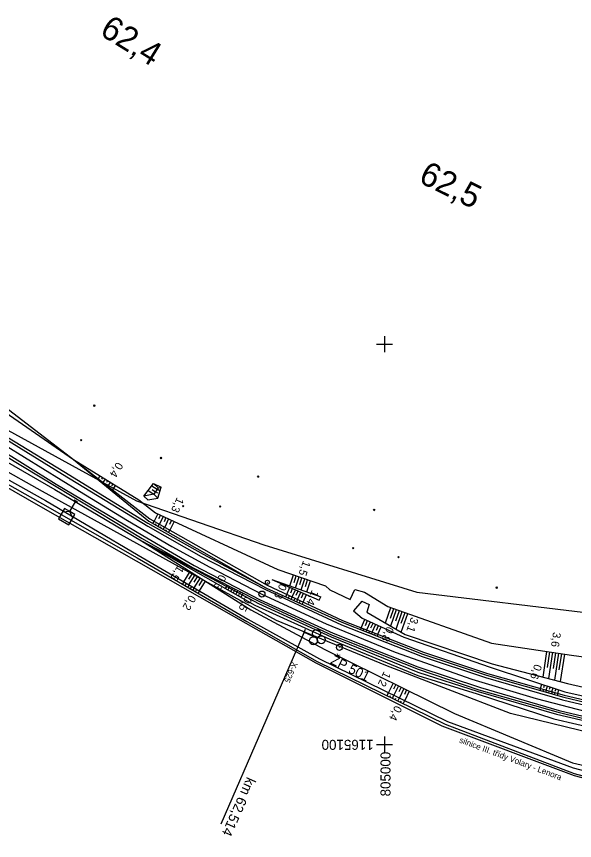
# Model space of a CAD drawing. Extents: x -805636 to -804553, y -1165340 to -1164656.
# Drawn here: x -805092 to -804952.6, y -1165124 to -1164918.2 of the extents above; entities that cross this region are included whole.
import ezdxf

# ---------------------------------------------------------------- set-up
doc = ezdxf.new("R2010")
doc.units = 0
for name, color, linetype in [('0381KM061-064P - Vrstva 1', 7, 'Continuous'), ('0381KM061-064P - Vrstva 4', 7, 'Continuous'), ('0381KM061-064P - Vrstva 48', 7, 'Continuous'), ('0381KM061-064P - Vrstva 49', 7, 'Continuous'), ('0381KM061-064P - Vrstva 51', 7, 'Continuous'), ('0381KM061-064P - Vrstva 7', 7, 'Continuous'), ('0381KM061-064P - Vrstva 8', 7, 'Continuous'), ('hran DP - hran DP', 7, 'Continuous'), ('krizky_1000 - souradnice', 7, 'Continuous'), ('krizky_1000 - Vrstva 1', 7, 'Continuous'), ('vyt_sit - stávající', 7, 'Continuous')]:
    doc.layers.add(name, color=color, linetype=linetype)

msp = doc.modelspace()

# ---------------------------------------------------------------- linework, layer by layer
at = {"layer": '0381KM061-064P - Vrstva 1'}
for points in [[(-805131.47, -1165002.7), (-805117.01, -1165011.6), (-805094.55, -1165025.46), (-805076.19, -1165036.77)], [(-805076.19, -1165036.77), (-805064.24, -1165044.04), (-805053.13, -1165050.53)], [(-805053.13, -1165050.53), (-805043.64, -1165055.76), (-805030.64, -1165062.45), (-805014.61, -1165069.88), (-804997.39, -1165076.92), (-804978.26, -1165083.66), (-804962.13, -1165088.54), (-804947.73, -1165092.28), (-804936.17, -1165094.91), (-804922.95, -1165097.46), (-804911.85, -1165099.22)]]:
    msp.add_lwpolyline(points, dxfattribs=at)
at = {"layer": '0381KM061-064P - Vrstva 4'}
for points in [[(-805257.4, -1164945.18), (-805227.5, -1164957.9), (-805205.55, -1164967.2), (-805161.7, -1164987.26), (-805121.4, -1165011.84), (-805082.08, -1165035.58)], [(-805257.21, -1164944.39), (-805227.21, -1164957.06), (-805205.17, -1164966.48), (-805161.59, -1164986.72), (-805120.84, -1165010.88), (-805082.03, -1165034.98)], [(-805187.57, -1164970.92), (-805160.12, -1164984.24), (-805119.58, -1165008.37), (-805080.47, -1165032.5)], [(-805187.4, -1164970.45), (-805159.98, -1164983.82), (-805119.44, -1165007.96), (-805080.11, -1165031.8)], [(-805080.11, -1165031.8), (-805059.18, -1165044.72), (-805045.31, -1165052.51), (-805029.54, -1165060.96), (-805010.72, -1165069.47), (-804990.45, -1165077.48), (-804974.57, -1165082.73), (-804955.28, -1165088.2), (-804932.96, -1165093.51), (-804912.39, -1165097.1), (-804892.28, -1165099.85)], [(-805080.47, -1165032.5), (-805059.19, -1165045.48), (-805045.86, -1165053.03), (-805029.76, -1165061.31), (-805010.76, -1165070.1), (-804990.66, -1165078.03), (-804974.85, -1165083.28), (-804955.57, -1165088.82), (-804933.31, -1165094.09), (-804912.36, -1165097.73), (-804892.37, -1165100.24)], [(-805082.08, -1165035.58), (-805060.58, -1165048.58), (-805047.98, -1165055.77), (-805031.23, -1165064.28), (-805013.07, -1165072.73), (-804991.62, -1165081.24), (-804976.47, -1165086.37), (-804956.64, -1165091.96), (-804934.05, -1165097.54), (-804913.13, -1165101.06), (-804892.22, -1165103.81)], [(-805082.03, -1165034.98), (-805060.37, -1165047.85), (-805047.54, -1165055.28), (-805031.06, -1165063.92), (-805012.89, -1165072.24), (-804991.69, -1165080.62), (-804976.05, -1165085.82), (-804956.42, -1165091.49), (-804933.87, -1165096.82), (-804912.82, -1165100.43), (-804892.24, -1165103.28)]]:
    msp.add_lwpolyline(points, dxfattribs=at)
at = {"layer": '0381KM061-064P - Vrstva 48'}
for p, q in [((-805071.7, -1165033.78), (-805071.58, -1165033.63)), ((-805071.12, -1165032.94), (-805071.56, -1165033.64)), ((-805070.48, -1165033.33), (-805070.72, -1165033.72)), ((-805069.84, -1165033.72), (-805070.36, -1165034.57)), ((-805071.12, -1165034.26), (-805071.05, -1165034.17)), ((-805070.54, -1165034.73), (-805070.39, -1165034.55)), ((-805069.96, -1165035.21), (-805069.88, -1165035.11)), ((-805069.21, -1165034.12), (-805069.49, -1165034.57)), ((-805069.38, -1165035.68), (-805069.2, -1165035.47)), ((-805068.57, -1165034.51), (-805069.17, -1165035.49)), ((-805067.93, -1165034.91), (-805068.25, -1165035.43)), ((-805067.29, -1165035.3), (-805067.98, -1165036.41)), ((-805058.16, -1165035.39), (-805056.82, -1165036.27)), ((-805068.8, -1165036.16), (-805068.71, -1165036.04)), ((-805068.22, -1165036.63), (-805068.02, -1165036.38)), ((-805059.08, -1165036.56), (-805057.62, -1165037.51)), ((-805058.06, -1165036.34), (-805057.22, -1165036.89)), ((-805056.69, -1165037.24), (-805057.22, -1165036.89)), ((-805056.11, -1165036.74), (-805056.82, -1165036.27)), ((-805056.69, -1165042.41), (-805057.55, -1165044.27)), ((-805056.01, -1165042.72), (-805056.45, -1165043.68)), ((-805055.32, -1165043.04), (-805056.24, -1165045.01)), ((-805054.64, -1165043.35), (-805055.11, -1165044.37)), ((-805053.96, -1165043.67), (-805054.93, -1165045.76)), ((-805053.28, -1165043.99), (-805053.78, -1165045.05)), ((-805057.91, -1165044.8), (-805057.59, -1165044.25)), ((-805057.26, -1165045.18), (-805057.1, -1165044.9)), ((-805056.61, -1165045.55), (-805056.29, -1165044.99)), ((-805055.96, -1165045.92), (-805055.8, -1165045.64)), ((-805055.31, -1165046.29), (-805054.98, -1165045.72)), ((-805052.6, -1165044.3), (-805053.62, -1165046.5)), ((-805054.65, -1165046.66), (-805054.49, -1165046.38)), ((-805054, -1165047.03), (-805053.68, -1165046.46)), ((-805050.18, -1165059.36), (-805048.58, -1165056.81)), ((-805048.9, -1165058.73), (-805047.94, -1165057.21)), ((-805048.89, -1165060.12), (-805047.31, -1165057.61)), ((-805047.61, -1165059.5), (-805046.68, -1165058.01)), ((-805047.59, -1165060.88), (-805046.04, -1165058.41)), ((-805023.71, -1165060.37), (-805022.78, -1165057.65)), ((-805022.63, -1165059.53), (-805022.07, -1165057.89)), ((-805022.3, -1165060.87), (-805021.36, -1165058.14)), ((-805021.22, -1165060.02), (-805020.66, -1165058.38)), ((-805020.89, -1165061.37), (-805019.95, -1165058.62)), ((-805050.16, -1165059.38), (-805050.49, -1165059.95)), ((-805049.64, -1165059.98), (-805049.84, -1165060.32)), ((-805048.86, -1165060.13), (-805049.19, -1165060.7)), ((-805046.33, -1165060.28), (-805045.41, -1165058.81)), ((-805046.29, -1165061.63), (-805044.77, -1165059.21)), ((-805039.53, -1165060.53), (-805039.82, -1165061.03)), ((-805039.51, -1165060.54), (-805039.32, -1165060.17)), ((-805038.77, -1165060.74), (-805038.65, -1165060.51)), ((-805019.81, -1165060.52), (-805019.24, -1165058.87)), ((-805019.48, -1165061.86), (-805018.53, -1165059.11)), ((-805048.35, -1165060.74), (-805048.55, -1165061.08)), ((-805047.57, -1165060.89), (-805047.9, -1165061.46)), ((-805047.05, -1165061.49), (-805047.25, -1165061.83)), ((-805046.27, -1165061.65), (-805046.6, -1165062.21)), ((-805038.99, -1165061.09), (-805039.17, -1165061.4)), ((-805038.21, -1165061.24), (-805038.52, -1165061.77)), ((-805038.18, -1165061.25), (-805037.98, -1165060.85)), ((-805037.68, -1165061.81), (-805037.86, -1165062.14)), ((-805037.44, -1165061.44), (-805037.31, -1165061.19)), ((-805036.89, -1165061.95), (-805037.21, -1165062.51)), ((-805036.86, -1165061.96), (-805036.64, -1165061.53)), ((-805036.36, -1165062.53), (-805036.56, -1165062.88)), ((-805036.11, -1165062.14), (-805035.97, -1165061.87)), ((-805035.57, -1165062.66), (-805035.91, -1165063.25)), ((-805035.54, -1165062.67), (-805035.3, -1165062.21)), ((-805024.47, -1165062.52), (-805024.74, -1165063.13)), ((-805024.46, -1165062.53), (-805023.69, -1165060.75)), ((-805023.47, -1165062.13), (-805023, -1165061.05)), ((-805023.1, -1165063.16), (-805022.31, -1165061.35)), ((-805022.1, -1165062.75), (-805021.62, -1165061.65)), ((-805021.74, -1165063.8), (-805020.94, -1165061.95)), ((-805020.74, -1165063.37), (-805020.25, -1165062.25)), ((-805020.39, -1165064.44), (-805019.56, -1165062.55)), ((-805023.9, -1165063.08), (-805024.06, -1165063.44)), ((-805023.11, -1165063.16), (-805023.37, -1165063.75)), ((-805022.53, -1165063.71), (-805022.69, -1165064.05)), ((-805021.75, -1165063.79), (-805022.01, -1165064.36)), ((-805021.17, -1165064.34), (-805021.32, -1165064.67)), ((-805020.39, -1165064.43), (-805020.64, -1165064.98)), ((-804999.81, -1165069.65), (-804998.44, -1165065.79)), ((-804998.58, -1165068.43), (-804997.73, -1165066.04)), ((-804998.48, -1165070.41), (-804997.03, -1165066.29)), ((-804997.22, -1165069.09), (-804996.32, -1165066.54)), ((-804997.16, -1165071.17), (-804995.61, -1165066.79)), ((-805005.89, -1165070.86), (-805004.93, -1165068.76)), ((-804995.86, -1165069.75), (-804994.91, -1165067.04)), ((-804995.84, -1165071.94), (-804994.2, -1165067.29)), ((-805005.88, -1165070.86), (-805006.06, -1165071.31)), ((-805004.81, -1165070.31), (-805004.25, -1165069.07)), ((-805004.49, -1165071.4), (-805003.57, -1165069.38)), ((-805003.43, -1165070.88), (-805002.89, -1165069.69)), ((-805003.1, -1165071.95), (-805002.21, -1165070)), ((-805002.05, -1165071.46), (-805001.53, -1165070.31)), ((-805001.7, -1165072.49), (-805000.85, -1165070.62)), ((-805005.26, -1165071.31), (-805005.36, -1165071.58)), ((-805004.49, -1165071.41), (-805004.67, -1165071.86)), ((-805003.86, -1165071.86), (-805003.97, -1165072.13)), ((-805003.09, -1165071.95), (-805003.27, -1165072.41)), ((-805002.46, -1165072.41), (-805002.57, -1165072.68)), ((-805001.69, -1165072.5), (-805001.88, -1165072.96)), ((-804960.43, -1165083.16), (-804959.47, -1165076.75)), ((-804959.31, -1165080.75), (-804958.72, -1165076.86)), ((-804958.97, -1165083.54), (-804957.98, -1165076.97)), ((-804957.84, -1165081.07), (-804957.24, -1165077.09)), ((-804957.51, -1165083.92), (-804956.5, -1165077.2)), ((-804956.37, -1165081.39), (-804955.76, -1165077.31)), ((-804956.05, -1165084.29), (-804955.02, -1165077.42)), ((-804997.87, -1165084.72), (-804999.02, -1165087.05)), ((-804997.2, -1165085.05), (-804997.77, -1165086.21)), ((-804996.53, -1165085.38), (-804997.68, -1165087.71)), ((-804961.1, -1165086), (-804960.76, -1165084.96)), ((-804960.24, -1165085.8), (-804960.04, -1165085.2)), ((-804999.41, -1165087.84), (-804999.02, -1165087.05)), ((-804995.85, -1165085.71), (-804996.43, -1165086.88)), ((-804995.18, -1165086.05), (-804996.33, -1165088.36)), ((-804994.51, -1165086.38), (-804995.08, -1165087.54)), ((-804993.84, -1165086.71), (-804994.98, -1165089.03)), ((-804961.08, -1165086.01), (-804961.22, -1165086.52)), ((-804960.41, -1165086.42), (-804960.5, -1165086.72)), ((-804959.63, -1165086.42), (-804959.78, -1165086.93)), ((-804959.66, -1165086.41), (-804959.33, -1165085.43)), ((-804958.97, -1165086.82), (-804959.06, -1165087.13)), ((-804958.81, -1165086.23), (-804958.62, -1165085.67)), ((-804958.19, -1165086.82), (-804958.34, -1165087.33)), ((-804958.21, -1165086.82), (-804957.91, -1165085.9)), ((-804957.53, -1165087.23), (-804957.62, -1165087.54)), ((-804957.37, -1165086.67), (-804957.2, -1165086.14)), ((-804956.75, -1165087.23), (-804956.89, -1165087.75)), ((-804956.77, -1165087.22), (-804956.48, -1165086.37)), ((-804998.73, -1165088.17), (-804998.54, -1165087.77)), ((-804998.06, -1165088.5), (-804997.67, -1165087.71)), ((-804997.39, -1165088.83), (-804997.19, -1165088.43)), ((-804996.71, -1165089.16), (-804996.32, -1165088.37)), ((-804996.04, -1165089.49), (-804995.84, -1165089.09)), ((-804995.36, -1165089.82), (-804994.98, -1165089.03))]:
    msp.add_line(p, q, dxfattribs=at)
at = {"layer": '0381KM061-064P - Vrstva 49'}
for p, q in [((-805072.34, -1165015.61), (-805072.69, -1165015.26)), ((-805072.34, -1165015.26), (-805072.69, -1165015.61)), ((-805075.64, -1165024.19), (-805076, -1165023.84)), ((-805075.64, -1165023.84), (-805076, -1165024.19)), ((-805055.69, -1165028.65), (-805056.04, -1165028.29)), ((-805055.69, -1165028.29), (-805056.04, -1165028.65)), ((-805031.42, -1165033.3), (-805031.77, -1165032.95)), ((-805031.42, -1165032.95), (-805031.77, -1165033.3)), ((-805050.15, -1165040.65), (-805050.5, -1165040.3)), ((-805050.15, -1165040.3), (-805050.5, -1165040.65)), ((-805040.91, -1165040.77), (-805041.26, -1165040.42)), ((-805040.91, -1165040.42), (-805041.26, -1165040.77)), ((-805002.45, -1165041.64), (-805002.8, -1165041.28)), ((-805002.45, -1165041.28), (-805002.8, -1165041.64)), ((-805007.66, -1165051.16), (-805008.02, -1165050.81)), ((-805007.66, -1165050.81), (-805008.02, -1165051.16)), ((-804996.38, -1165053.38), (-804996.73, -1165053.03)), ((-804996.38, -1165053.03), (-804996.73, -1165053.38)), ((-804971.83, -1165061.04), (-804972.19, -1165060.69)), ((-804971.83, -1165060.69), (-804972.19, -1165061.04)), ((-805029.54, -1165060.96), (-805010.72, -1165069.47))]:
    msp.add_line(p, q, dxfattribs=at)
for points in [[(-805254.52, -1164927.32), (-805250.48, -1164933.58), (-805239.73, -1164938.85), (-805217.98, -1164949.5), (-805160.38, -1164977.95), (-805138.64, -1164988.6), (-805110.66, -1165003.53), (-805077.76, -1165028.83)], [(-805234.27, -1164967.17), (-805220.67, -1164970.52), (-805207.94, -1164974.16), (-805191.02, -1164980.42), (-805165.29, -1164994.07), (-805122, -1165019.23), (-805085.43, -1165039.91)], [(-805234.06, -1164966.19), (-805220.55, -1164969.15), (-805207.89, -1164972.65), (-805190.88, -1164979.53), (-805164.65, -1164993.41), (-805121.85, -1165018.34), (-805084.74, -1165039.06)], [(-805205.55, -1164967.2), (-805162.48, -1164988.88), (-805121.89, -1165013.64), (-805082.35, -1165036.29)], [(-805185.93, -1164967.81), (-805156.92, -1164981.59), (-805111.71, -1165005.38), (-805077.76, -1165028.83)], [(-805077.76, -1165028.83), (-805058.62, -1165043.66), (-805029.31, -1165060.25)], [(-805077.76, -1165028.83), (-805061.41, -1165038.93), (-805057.27, -1165042.14), (-805026.66, -1165056.32), (-805014.74, -1165060.42)], [(-805077.76, -1165028.83), (-805058.9, -1165044.24), (-805029.54, -1165060.96)], [(-805060.16, -1165037.96), (-805057.76, -1165034.87)], [(-805057.76, -1165034.87), (-805055.79, -1165035.72)], [(-805056.55, -1165035.87), (-805057.76, -1165034.87)], [(-805056.55, -1165035.87), (-805057.62, -1165037.51)], [(-805056.65, -1165038.5), (-805055.79, -1165035.72)], [(-805056.55, -1165035.87), (-805055.79, -1165035.72)], [(-805082.35, -1165036.29), (-805060.73, -1165049.17)], [(-805057.62, -1165037.51), (-805060.16, -1165037.96)], [(-805060.16, -1165037.96), (-805059.18, -1165038.9), (-805056.65, -1165038.5)], [(-805057.62, -1165037.51), (-805056.65, -1165038.5)], [(-805085.43, -1165039.91), (-805061.8, -1165053.37), (-805034.45, -1165069.27), (-805016.82, -1165079.3), (-804984.87, -1165094.97), (-804952.63, -1165107.29), (-804923.66, -1165115.02), (-804890.91, -1165119.51), (-804860.93, -1165120.87), (-804821.85, -1165122.9), (-804805.33, -1165123.27)], [(-805084.74, -1165039.06), (-805061.55, -1165052.74), (-805034.17, -1165068.7), (-805016.31, -1165078.58), (-804984.31, -1165094.26), (-804952.92, -1165105.84), (-804923.4, -1165113.55), (-804890.69, -1165118.62), (-804860.79, -1165119.97), (-804821.99, -1165121.8), (-804804.98, -1165122.47)], [(-805060.73, -1165049.17), (-805031.5, -1165064.84), (-805013.36, -1165073.14), (-804991.7, -1165081.91), (-804976.67, -1165086.76), (-804957.06, -1165092.46), (-804934.14, -1165097.81), (-804913.12, -1165101.52), (-804892.37, -1165104.14)], [(-805060.73, -1165049.17), (-805032.39, -1165065.25)], [(-805060.73, -1165049.17), (-805033.41, -1165066.35)], [(-805060.73, -1165049.17), (-805047.98, -1165055.77), (-805031.23, -1165064.28), (-805013.07, -1165072.73), (-804991.62, -1165081.24), (-804976.47, -1165086.37), (-804956.64, -1165091.96), (-804934.05, -1165097.54), (-804913.13, -1165101.06), (-804892.22, -1165103.81), (-804860.51, -1165107.09), (-804841.9, -1165109.22), (-804820.58, -1165111.74), (-804811.31, -1165113.56)], [(-805029.31, -1165060.25), (-805010.57, -1165069.03), (-804990.26, -1165076.95), (-804974.29, -1165082.29), (-804955.12, -1165087.69)], [(-805028.22, -1165058.77), (-805015.98, -1165063.1)], [(-805028.22, -1165058.77), (-805016.34, -1165063.96)], [(-805014.74, -1165060.42), (-805013.72, -1165061.35), (-805008.65, -1165063.79), (-805007.41, -1165061.32), (-805005.07, -1165061.94), (-804999.18, -1165065.52), (-804973.34, -1165074.67), (-804953.36, -1165077.67), (-804930.03, -1165080.86)], [(-805016.34, -1165063.96), (-805015.98, -1165063.1)], [(-805005.66, -1165064.21), (-805007.76, -1165066.63), (-805005.59, -1165068.46), (-804995.17, -1165073.22)], [(-805005.66, -1165064.21), (-805003.85, -1165065.08), (-805004.43, -1165066.97), (-804994.86, -1165072.51)], [(-805033.41, -1165066.35), (-805014.98, -1165076.25), (-804982.53, -1165092.31), (-804953.12, -1165104.6), (-804922.96, -1165111.59), (-804890.43, -1165117.32), (-804859.92, -1165117.39), (-804821.94, -1165119.94), (-804804.42, -1165121.15)], [(-805032.39, -1165065.25), (-805013.72, -1165073.73), (-804991.69, -1165082.79), (-804976.92, -1165087.4), (-804957.71, -1165093.59), (-804934.8, -1165098.93), (-804913.68, -1165102.56), (-804892.44, -1165105.41)], [(-805010.72, -1165069.47), (-804990.45, -1165077.48), (-804974.57, -1165082.73), (-804955.28, -1165088.2), (-804932.96, -1165093.51), (-804912.39, -1165097.1), (-804892.28, -1165099.85), (-804859.81, -1165103.25), (-804840.34, -1165105.46), (-804819.52, -1165107.92), (-804802.69, -1165109.64), (-804799.68, -1165110)], [(-804994.86, -1165072.51), (-804973.16, -1165079.86), (-804954.29, -1165084.75), (-804932.5, -1165089.79), (-804920.22, -1165090.5), (-804911.77, -1165084.22), (-804893.29, -1165083.05), (-804876.57, -1165085.04), (-804853.44, -1165091.21), (-804839.72, -1165094.63), (-804814.35, -1165098.18)], [(-804995.17, -1165073.22), (-804973.67, -1165080.7), (-804954.98, -1165086.86), (-804932.57, -1165091.85), (-804911.87, -1165094.85)], [(-804955.12, -1165087.69), (-804932.8, -1165092.95), (-804911.98, -1165096.48), (-804892.31, -1165098.96)]]:
    msp.add_lwpolyline(points, dxfattribs=at)
at = {"layer": '0381KM061-064P - Vrstva 51'}
for points in [[(-805234.38, -1164968.09), (-805220.73, -1164971.11), (-805207.78, -1164974.89), (-805191.18, -1164980.95), (-805165.61, -1164994.58), (-805122.14, -1165019.85), (-805085.93, -1165040.55)], [(-805085.93, -1165040.55), (-805062.08, -1165054.12), (-805034.69, -1165069.73), (-805017.21, -1165079.65), (-804985.71, -1165095.39), (-804952.66, -1165107.75), (-804923.93, -1165115.31), (-804890.75, -1165120.1), (-804861.18, -1165121.85), (-804821.92, -1165123.67), (-804805.64, -1165124)]]:
    msp.add_lwpolyline(points, dxfattribs=at)
at = {"layer": '0381KM061-064P - Vrstva 7'}
for p, q in [((-805078.64, -1165041.84), (-805077.12, -1165039.26)), ((-805076.69, -1165039.51), (-805077.56, -1165039)), ((-805029.33, -1165059.48), (-805029.24, -1165059.53))]:
    msp.add_line(p, q, dxfattribs=at)
for points in [[(-805078.64, -1165041.84), (-805079.94, -1165041.08), (-805081.46, -1165043.67), (-805078.87, -1165045.19), (-805077.35, -1165042.6), (-805078.64, -1165041.84)], [(-805077.86, -1165043.47), (-805078.64, -1165041.84), (-805080.45, -1165041.95)]]:
    msp.add_lwpolyline(points, dxfattribs=at)
for centre, radius in [((-805029.29, -1165059.51), 0.5), ((-805030.64, -1165062.45), 0.75)]:
    msp.add_circle(centre, radius, dxfattribs=at)
at = {"layer": '0381KM061-064P - Vrstva 8'}
for p, q in [((-805020.14, -1165071.99), (-805040.91, -1165119.94)), ((-805019.84, -1165071.3), (-805020.44, -1165072.67)), ((-805020.14, -1165071.99), (-805017.39, -1165073.18))]:
    msp.add_line(p, q, dxfattribs=at)
for centre in [(-805016.99, -1165072.26), (-805015.83, -1165073.86), (-805017.79, -1165074.1)]:
    msp.add_circle(centre, 1, dxfattribs=at)
at = {"layer": 'hran DP - hran DP'}
for p, q in [((-805100.45, -1165018.04), (-805061.96, -1165039.19)), ((-805085.48, -1165036.81), (-805115.56, -1165019.91)), ((-805027.03, -1165069.02), (-805085.48, -1165036.81)), ((-805061.96, -1165039.19), (-805030.17, -1165050.11)), ((-805030.17, -1165050.11), (-804991.93, -1165061.99)), ((-804991.93, -1165061.99), (-804883.1, -1165075.15)), ((-804999.74, -1165080.26), (-805027.03, -1165069.02)), ((-804968.55, -1165092.26), (-804999.74, -1165080.26)), ((-804934.32, -1165100.62), (-804968.55, -1165092.26))]:
    msp.add_line(p, q, dxfattribs=at)
at = {"layer": 'krizky_1000 - Vrstva 1'}
for points in [[(-805000, -1164998), (-805000, -1165002)], [(-805002, -1165000), (-804998, -1165000)], [(-805000, -1165098), (-805000, -1165102)], [(-805002, -1165100), (-804998, -1165100)]]:
    msp.add_lwpolyline(points, dxfattribs=at)
at = {"layer": 'vyt_sit - stávající'}
msp.add_line((-805011.33, -1165075.72), (-805011.24, -1165075.78), dxfattribs=at)
msp.add_circle((-805011.29, -1165075.75), 0.756, dxfattribs=at)

# ---------------------------------------------------------------- texts
at = {"layer": '0381KM061-064P - Vrstva 48'}
for s, rotation, p in [('0,4', 238.304, (-805066.88, -1165029.32)), ('1,3', 245.1485, (-805051.84, -1165038.14)), ('1,5', 251.0215, (-805020.34, -1165053.96)), ('1,5', 237.8283, (-805051.65, -1165055.14)), ('0,3', 245.683, (-805041.29, -1165057.41)), ('0,3', 245.683, (-805026.16, -1165059.68)), ('1,4', 246.405, (-805018.15, -1165061.28)), ('0,2', 239.8249, (-805048.7, -1165062.53)), ('0,5', 240.4291, (-805034.77, -1165062.85)), ('3,1', 250.5147, (-804993.36, -1165068.06)), ('0,8', 245.4289, (-804999.39, -1165070.38)), ('3,6', 261.4565, (-804957.92, -1165071.85)), ('0,6', 251.7483, (-804962.54, -1165079.81)), ('1,2', 243.6728, (-805000.13, -1165081.62)), ('0,4', 243.8879, (-804997.36, -1165090.12))]:
    msp.add_text(s, height=2, rotation=rotation, dxfattribs=at).set_placement(p)
at = {"layer": '0381KM061-064P - Vrstva 51'}
msp.add_text('silnice III. třídy Volary - Lenora', height=1.5, rotation=339.5082, dxfattribs=at).set_placement((-804981.49, -1165099.49))
at = {"layer": '0381KM061-064P - Vrstva 7'}
for s, rotation, p in [('62,4', 328.3477, (-805071.45, -1164922.62)), ('62,5', 333.6639, (-804991.8, -1164959.45))]:
    msp.add_text(s, height=6, rotation=rotation, dxfattribs=at).set_placement(p)
at = {"layer": '0381KM061-064P - Vrstva 8'}
for s, height, rotation, p in [('X-625', 1.5, 246.0395, (-805023.02, -1165079.26)), ('km 62,514', 2.5, 245.9676, (-805034.38, -1165107.96))]:
    msp.add_text(s, height=height, rotation=rotation, dxfattribs=at).set_placement(p)
at = {"layer": 'krizky_1000 - souradnice'}
for s, rotation, p in [('1165100', 180, (-805002.74, -1165098.85)), ('805000', 90, (-804998.54, -1165112.98))]:
    msp.add_text(s, height=2.5, rotation=rotation, dxfattribs=at).set_placement(p)
at = {"layer": 'vyt_sit - stávající'}
msp.add_text('ŽP 501', height=2.4, rotation=333.5611, dxfattribs=at).set_placement((-805013.74, -1165079.72))

doc.saveas('drawing.dxf')
